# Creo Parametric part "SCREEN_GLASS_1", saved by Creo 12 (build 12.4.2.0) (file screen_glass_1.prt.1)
Units: Custom; MM, KILOGRAM, SECS

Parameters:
  PTC_WM_ITERATION = "0"
  PTC_WM_VERSION = "-.0"
  PTC_WM_LIFECYCLE_STATE = "In Work"
  PTC_WM_LIFECYCLE = "MO_CADDocument"
  PTC_WM_CREATED_BY = "Maximilian Roepper (Z0017RMS: MO)"
  PTC_WM_CREATED_ON = "18-Sep-26 11:36:42 AM"
  PTC_WM_MODIFIED_BY = "Maximilian Roepper (Z0017RMS: MO)"
  PTC_WM_MODIFIED_ON = "18-Sep-26 11:36:46 AM"
  PDMLINKNUMBER = "PDM000071455070"
  PTC_WM_NAME = "screen_glass_1.prt"
  PTC_WM_NUMBER = "PDM000071455070"

Other parameters: WEIGHT, WEIGHT_FACTOR, WEIGHT_ADD, _MASS_TEMP, _DIFF_TEMP, MC_ERRORS, SUPPLIER

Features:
  1. coordinate system
  2. datum plane "PRT_YZ"
  3. datum plane "PRT_XY"
  4. datum plane "PRT_XZ"
  5. coordinate system
  6. datum axis
  7. datum axis
  8. datum axis
  9. coordinate system
  10. imported feature

Other named items: PRT, SIEMENS_MO, DRW_VIEW_ORG, PRT_X, PRT_Y, PRT_Z, CS0, ROUGH_GROB

Layers: 00_STD_CSYS-KSYS, 01_STD_PLANES-EBENEN, 02_STD_AXES-ACHSEN, 03_STD_CSYS-KSYS, 24_IMPORT_FEAT-IMPORT_KE

Surfaces: 6 plane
